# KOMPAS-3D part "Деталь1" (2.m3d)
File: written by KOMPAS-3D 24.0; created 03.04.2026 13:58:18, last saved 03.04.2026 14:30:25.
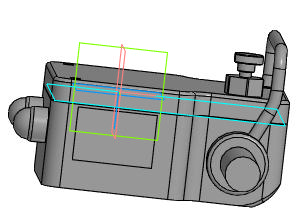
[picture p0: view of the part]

Document properties: Автор: R2D2; Полное имя файла: E:\Работа\Зайцев\Аксессуары для пневмоприводов\Ручной дублер DN.ru\MON2-450-T28-ISO Ручной дублер DN.ru\исходные материалы\2.m3d

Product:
- Body: Тело 2  | qty 1
    Масса: 7.905441
- Part/product: Деталь1
    Масса: 10.922817
    additional columns: Типовые

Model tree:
1. Операция без истории:1
2. Эскиз:1  (with: Ребро.Операция без истории:1)
3. Элемент выдавливания:3
     Расстояние 1 = 500
4. Эскиз:3  (with: Грань.Элемент выдавливания:3)
5. Элемент выдавливания:4  (with: Грань.Операция без истории:1)
     Расстояние 1 = 10
6. Эскиз:4
7. Элемент выдавливания:5
     Расстояние 1 = 500
8. Смещенная плоскость:1  (with: Грань.Операция без истории:1)
     Расстояние = 13
9. Эскиз:5  (with: Ребро.Операция без истории:1)
10. Элемент выдавливания:6
     Расстояние 2 = 0.5
11. Элемент выдавливания:7  (with: Грань.Операция без истории:1)
     Расстояние 1 = 0.5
